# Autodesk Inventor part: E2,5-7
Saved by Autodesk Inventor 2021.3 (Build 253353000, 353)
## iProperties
Created: 2021-12
Part Number: E2,5-7
Material: Generic
Document SubType Name: Modeling
Designer: Administrator
Density: 1 g/cm^3
Appearance: Default
Title: E2,5-7
Author: Administrator
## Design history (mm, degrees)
feature "Body1"
body "Solid1"
